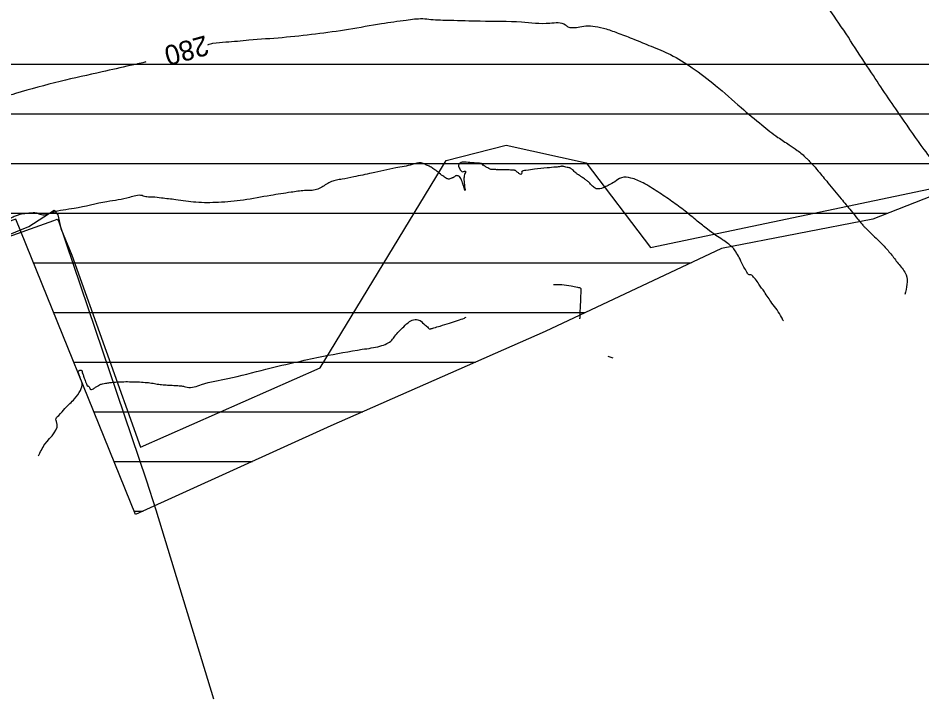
# Model space of a CAD drawing. Extents: x -478464 to -472469, y -1118040 to -1113785.
# Drawn here: x -475759.9 to -475577.7, y -1116153.7 to -1116016.6 of the extents above; entities that cross this region are included whole.
import ezdxf

# ---------------------------------------------------------------- set-up
doc = ezdxf.new("R2010")
doc.units = 0
for name, color, linetype in [('meliorace', 7, 'Continuous'), ('ObPÚ', 7, 'Continuous'), ('VAK_vodovod', 7, 'Continuous'), ('Vrstevnice_hlavni', 7, 'Continuous'), ('Vrstevnice_popis', 7, 'Continuous'), ('Vrstevnice_vedlejsi', 7, 'Continuous')]:
    doc.layers.add(name, color=color, linetype=linetype)

msp = doc.modelspace()

# ---------------------------------------------------------------- linework, layer by layer
at = {"layer": 'meliorace'}
for p, q in [((-475823.626, -1116025.871), (-475330.049, -1116025.871)), ((-475820.488, -1116035.871), (-475318.229, -1116035.871)), ((-475817.351, -1116045.871), (-475309.213, -1116045.871)), ((-475814.214, -1116055.871), (-475584.63, -1116055.871)), ((-475756.779, -1116065.871), (-475624.244, -1116065.871)), ((-475752.725, -1116075.871), (-475645.578, -1116075.871)), ((-475748.672, -1116085.871), (-475667.738, -1116085.871)), ((-475744.619, -1116095.871), (-475690.405, -1116095.871)), ((-475740.565, -1116105.871), (-475712.626, -1116105.871)), ((-475736.512, -1116115.871), (-475734.671, -1116115.871))]:
    msp.add_line(p, q, dxfattribs=at)
msp.add_lwpolyline([(-475572.396, -1116051.092), (-475587.636, -1116057.045), (-475618.116, -1116062.998), (-475653.676, -1116079.667), (-475696.856, -1116098.717), (-475736.226, -1116116.576), (-475760.356, -1116057.045), (-475808.616, -1116073.714), (-475834.016, -1115992.751), (-475842.906, -1115992.751), (-475865.766, -1115949.889), (-475890.404, -1115904.645)], dxfattribs=at)
at = {"layer": 'ObPÚ'}
msp.add_lwpolyline([(-475793.58, -1116073.18), (-475757.75, -1116058.57), (-475752.61, -1116055.25), (-475751.89, -1116056.2), (-475751.3, -1116058.92), (-475749.06, -1116064.34), (-475735.22, -1116102.98), (-475699.02, -1116087.04), (-475673.65, -1116045.26), (-475661.5, -1116042.18), (-475645.43, -1116045.73), (-475632.45, -1116062.75), (-475547.58, -1116044.99)], dxfattribs=at)
at = {"layer": 'VAK_vodovod'}
for points in [[(-475889.88, -1116108.469), (-475889.59, -1116108.35), (-475844.989, -1116090.309), (-475752.719, -1116057.309), (-475752.027, -1116057.077)], [(-475752.027, -1116057.077), (-475751.789, -1116057.42), (-475734.09, -1116109.6), (-475732.17, -1116115.59), (-475720.526, -1116153.696)]]:
    msp.add_lwpolyline(points, dxfattribs=at)
at = {"layer": 'Vrstevnice_hlavni'}
for points in [[(-475467.419, -1116061.098), (-475468.792, -1116057.501), (-475469.738, -1116055.712), (-475470.944, -1116053.934), (-475472.408, -1116052.165), (-475473.807, -1116050.611), (-475475.141, -1116049.271), (-475476.41, -1116048.144), (-475477.843, -1116046.826), (-475479.442, -1116045.315), (-475481.205, -1116043.613), (-475482.586, -1116042.213), (-475483.586, -1116041.117), (-475484.203, -1116040.325), (-475484.728, -1116039.713), (-475485.161, -1116039.283), (-475485.501, -1116039.033), (-475486.369, -1116038.386), (-475487.765, -1116037.341), (-475489.689, -1116035.897), (-475492.224, -1116033.125), (-475495.368, -1116029.023), (-475499.122, -1116023.591), (-475503.303, -1116017.953), (-475507.911, -1116012.107), (-475512.947, -1116006.053), (-475516.528, -1116001.592), (-475518.655, -1115998.722), (-475519.327, -1115997.444), (-475520.958, -1115993.755), (-475523.546, -1115987.656), (-475527.091, -1115979.146), (-475530.068, -1115972.249), (-475532.475, -1115966.964), (-475534.314, -1115963.291), (-475536.317, -1115958.959), (-475538.485, -1115953.967), (-475540.818, -1115948.316), (-475544.241, -1115943.054), (-475548.756, -1115938.18), (-475554.361, -1115933.695), (-475559.671, -1115929.584), (-475564.686, -1115925.845), (-475569.406, -1115922.48), (-475575.428, -1115918.124), (-475582.751, -1115912.777), (-475591.375, -1115906.439), (-475598.808, -1115901.664), (-475605.049, -1115898.45), (-475610.098, -1115896.799), (-475615.266, -1115895.356), (-475620.552, -1115894.121), (-475631.362, -1115892.07)], [(-475721.656, -1116021.921), (-475720.62, -1116021.633), (-475718.031, -1116021.363), (-475713.372, -1116020.965), (-475706.644, -1116020.44), (-475699.945, -1116019.714), (-475693.277, -1116018.786), (-475686.638, -1116017.656), (-475681.664, -1116016.951), (-475678.354, -1116016.672), (-475676.708, -1116016.818), (-475672.839, -1116016.975), (-475666.748, -1116017.142), (-475658.434, -1116017.321), (-475652.719, -1116017.574), (-475649.603, -1116017.901), (-475649.085, -1116018.302), (-475648.228, -1116018.475), (-475647.031, -1116018.42), (-475645.495, -1116018.137), (-475643.612, -1116018.247), (-475641.384, -1116018.748), (-475638.81, -1116019.641), (-475635.789, -1116020.801), (-475632.319, -1116022.229), (-475628.402, -1116023.923), (-475624.07, -1116026.55), (-475619.323, -1116030.11), (-475614.162, -1116034.601), (-475609.969, -1116038.094), (-475606.743, -1116040.588), (-475604.485, -1116042.082), (-475602.862, -1116043.199), (-475601.875, -1116043.937), (-475601.523, -1116044.296), (-475601.083, -1116044.742), (-475600.556, -1116045.273), (-475599.94, -1116045.889), (-475598.642, -1116047.373), (-475596.662, -1116049.725), (-475594.001, -1116052.945), (-475592.012, -1116055.361), (-475590.694, -1116056.974), (-475590.049, -1116057.784), (-475589.53, -1116058.403), (-475589.136, -1116058.832), (-475588.867, -1116059.071), (-475588.149, -1116059.767), (-475586.98, -1116060.92), (-475585.362, -1116062.531), (-475583.813, -1116064.295), (-475582.333, -1116066.213), (-475580.922, -1116068.285), (-475581.168, -1116072.263)], [(-475734.144, -1116025.39), (-475734.387, -1116025.457), (-475737.287, -1116026.117), (-475742.967, -1116027.402), (-475751.425, -1116029.313), (-475760.397, -1116031.757), (-475769.883, -1116034.735), (-475779.883, -1116038.248), (-475786.895, -1116040.679), (-475790.919, -1116042.028), (-475791.955, -1116042.297), (-475792.697, -1116042.52), (-475793.144, -1116042.699), (-475793.297, -1116042.833), (-475793.588, -1116043.024), (-475794.017, -1116043.273), (-475794.584, -1116043.58), (-475795.952, -1116044.161), (-475798.119, -1116045.015), (-475801.087, -1116046.144), (-475804.225, -1116047.876), (-475807.532, -1116050.21), (-475811.009, -1116053.146), (-475814.071, -1116055.662), (-475816.718, -1116057.758), (-475818.95, -1116059.434), (-475821.025, -1116061.042), (-475822.943, -1116062.582), (-475824.704, -1116064.055), (-475826.102, -1116065.24), (-475827.136, -1116066.137), (-475827.806, -1116066.746), (-475828.232, -1116067.209), (-475828.413, -1116067.526), (-475828.351, -1116067.695), (-475828.313, -1116067.833), (-475828.301, -1116067.938), (-475828.314, -1116068.011), (-475828.374, -1116068.106), (-475828.48, -1116068.222), (-475828.632, -1116068.36), (-475828.838, -1116068.557), (-475829.097, -1116068.811), (-475829.411, -1116069.123), (-475829.283, -1116069.23), (-475828.713, -1116069.131), (-475827.701, -1116068.826), (-475826.629, -1116068.71), (-475825.498, -1116068.782), (-475824.306, -1116069.042), (-475823.632, -1116070.151), (-475823.476, -1116072.107), (-475823.837, -1116074.911), (-475824.33, -1116076.913), (-475824.954, -1116078.115), (-475825.71, -1116078.516), (-475826.49, -1116078.935), (-475827.294, -1116079.372), (-475828.122, -1116079.828), (-475829.743, -1116080.299), (-475832.155, -1116080.784), (-475835.36, -1116081.285), (-475837.985, -1116081.623), (-475840.031, -1116081.798), (-475841.497, -1116081.812), (-475842.513, -1116081.989), (-475843.078, -1116082.332), (-475843.194, -1116082.84), (-475843.394, -1116083.435), (-475843.681, -1116084.119), (-475844.052, -1116084.891), (-475844.462, -1116085.311), (-475844.911, -1116085.379), (-475845.399, -1116085.096), (-475845.763, -1116084.899), (-475846.004, -1116084.788), (-475846.121, -1116084.764), (-475846.236, -1116084.79), (-475846.348, -1116084.866), (-475846.459, -1116084.992), (-475846.998, -1116085.894), (-475847.966, -1116087.573), (-475849.364, -1116090.027), (-475850.298, -1116091.666), (-475850.771, -1116092.488), (-475850.781, -1116092.494), (-475850.786, -1116092.51), (-475850.787, -1116092.538), (-475850.784, -1116092.577), (-475850.701, -1116092.72), (-475850.538, -1116092.969), (-475850.294, -1116093.322), (-475849.947, -1116093.789), (-475849.495, -1116094.37), (-475848.939, -1116095.066), (-475848.819, -1116095.385), (-475849.137, -1116095.329)]]:
    msp.add_spline(points, degree=3, dxfattribs=at)
at = {"layer": 'Vrstevnice_vedlejsi'}
msp.add_line((-475641.018, -1116084.677), (-475640.054, -1116085.004), dxfattribs=at)
for points in [[(-475480.151, -1116069.925), (-475480.528, -1116069.421), (-475481.823, -1116067.661), (-475483.652, -1116064.935), (-475486.015, -1116061.242), (-475488.912, -1116056.583), (-475491.25, -1116052.905), (-475493.027, -1116050.207), (-475494.244, -1116048.489), (-475495.061, -1116047.336), (-475495.479, -1116046.748), (-475495.497, -1116046.725), (-475495.829, -1116046.475), (-475496.475, -1116045.999), (-475497.435, -1116045.295), (-475499.886, -1116043.467), (-475503.828, -1116040.516), (-475509.26, -1116036.441), (-475513.121, -1116033.379), (-475515.41, -1116031.328), (-475516.128, -1116030.289), (-475516.97, -1116029.159), (-475517.937, -1116027.939), (-475519.028, -1116026.627), (-475521.605, -1116022.94), (-475525.669, -1116016.877), (-475531.218, -1116008.438), (-475535.677, -1116000.991), (-475539.045, -1115994.534), (-475541.323, -1115989.067), (-475544.201, -1115982.706), (-475547.68, -1115975.451), (-475551.759, -1115967.302), (-475554.612, -1115961.548), (-475556.237, -1115958.188), (-475556.636, -1115957.222), (-475557.22, -1115956.323), (-475557.991, -1115955.491), (-475558.949, -1115954.725), (-475561.753, -1115952.67), (-475566.405, -1115949.326), (-475572.904, -1115944.692), (-475579.584, -1115939.938), (-475586.446, -1115935.063), (-475593.49, -1115930.068), (-475600.006, -1115926.174), (-475605.993, -1115923.382)], [(-475497.37, -1116068.403), (-475497.633, -1116067.979), (-475500.085, -1116064.037), (-475501.869, -1116061.198), (-475502.986, -1116059.46), (-475503.436, -1116058.825), (-475503.924, -1116058.233), (-475504.45, -1116057.685), (-475505.013, -1116057.18), (-475505.755, -1116056.024), (-475506.678, -1116054.215), (-475507.779, -1116051.755), (-475508.673, -1116049.954), (-475509.359, -1116048.814), (-475509.837, -1116048.333), (-475511.119, -1116047.79), (-475513.205, -1116047.187), (-475516.096, -1116046.522), (-475518.059, -1116046.071), (-475519.096, -1116045.833), (-475519.205, -1116045.808), (-475519.283, -1116045.788), (-475519.33, -1116045.772), (-475519.346, -1116045.76), (-475520.304, -1116045.057), (-475522.205, -1116043.664), (-475525.048, -1116041.58), (-475527.874, -1116039.592), (-475530.681, -1116037.698), (-475533.471, -1116035.9), (-475536.828, -1116031.824), (-475540.751, -1116025.472), (-475545.242, -1116016.842), (-475548.836, -1116010.176), (-475551.533, -1116005.475), (-475553.333, -1116002.737), (-475554.692, -1116000.531), (-475555.61, -1115998.855), (-475556.087, -1115997.71), (-475556.784, -1115996.19), (-475557.701, -1115994.295), (-475558.837, -1115992.025), (-475562.469, -1115987.267), (-475568.595, -1115980.022), (-475577.217, -1115970.289), (-475584.87, -1115962.449), (-475591.555, -1115956.502), (-475597.272, -1115952.448), (-475603.006, -1115949.149), (-475608.756, -1115946.607), (-475614.524, -1115944.82), (-475620.596, -1115943.36), (-475626.972, -1115942.227)], [(-475517.572, -1116066.619), (-475517.753, -1116066.428), (-475521.164, -1116062.876), (-475524.777, -1116059.186), (-475527.496, -1116056.526), (-475529.321, -1116054.896), (-475530.252, -1116054.296), (-475531.462, -1116053.606), (-475532.952, -1116052.825), (-475534.721, -1116051.953), (-475536.209, -1116051.042), (-475537.415, -1116050.093), (-475538.339, -1116049.106), (-475539.112, -1116048.345), (-475539.734, -1116047.811), (-475540.205, -1116047.503), (-475540.671, -1116047.258), (-475541.132, -1116047.075), (-475541.589, -1116046.955), (-475543.06, -1116046.13), (-475545.544, -1116044.599), (-475549.042, -1116042.364), (-475551.91, -1116040.528), (-475554.148, -1116039.093), (-475555.755, -1116038.057), (-475557.153, -1116036.738), (-475558.342, -1116035.138), (-475559.321, -1116033.256), (-475562.018, -1116028.66), (-475566.432, -1116021.35), (-475572.564, -1116011.326), (-475579.461, -1116001.664), (-475587.123, -1115992.364), (-475595.552, -1115983.426), (-475602.158, -1115977.054), (-475606.943, -1115973.249), (-475609.906, -1115972.01), (-475614.951, -1115970.845), (-475622.078, -1115969.752), (-475631.287, -1115968.732), (-475641.35, -1115967.924), (-475652.265, -1115967.327), (-475664.034, -1115966.942), (-475672.102, -1115966.665), (-475676.468, -1115966.495), (-475677.132, -1115966.434), (-475678.388, -1115966.326), (-475680.235, -1115966.172), (-475682.675, -1115965.971), (-475688.18, -1115965.51), (-475696.749, -1115964.79)], [(-475546.909, -1116064.851), (-475548.498, -1116064.079), (-475551.049, -1116062.628), (-475553.948, -1116060.801), (-475557.196, -1116058.596), (-475559.728, -1116056.751), (-475561.543, -1116055.266), (-475562.643, -1116054.14), (-475563.681, -1116053.352), (-475564.658, -1116052.9), (-475565.574, -1116052.785), (-475566.693, -1116052.522), (-475568.017, -1116052.111), (-475569.545, -1116051.551), (-475571.597, -1116049.847), (-475574.173, -1116046.997), (-475577.272, -1116043.003), (-475581.846, -1116036.534), (-475587.894, -1116027.591), (-475595.416, -1116016.174), (-475600.541, -1116008.467), (-475603.269, -1116004.469), (-475603.6, -1116004.181), (-475604.124, -1116003.858), (-475604.841, -1116003.499), (-475605.751, -1116003.105), (-475609.228, -1116001.643), (-475615.272, -1115999.112), (-475623.883, -1115995.513), (-475630.473, -1115993.019), (-475635.042, -1115991.631)], [(-475658.86, -1116047.938), (-475659.29, -1116047.586), (-475659.587, -1116047.351), (-475659.75, -1116047.232), (-475659.778, -1116047.229), (-475659.985, -1116047.214), (-475660.371, -1116047.188), (-475660.937, -1116047.15), (-475661.516, -1116047.122), (-475662.11, -1116047.105), (-475662.719, -1116047.097), (-475663.129, -1116047.093), (-475663.34, -1116047.092), (-475663.353, -1116047.093), (-475663.496, -1116047.092), (-475663.77, -1116047.087), (-475664.174, -1116047.079), (-475664.455, -1116047.072), (-475664.613, -1116047.064), (-475664.648, -1116047.056), (-475664.861, -1116046.945), (-475665.254, -1116046.73), (-475665.825, -1116046.412), (-475666.185, -1116046.197), (-475666.335, -1116046.086), (-475666.275, -1116046.078), (-475666.267, -1116046.047), (-475666.312, -1116045.993), (-475666.41, -1116045.917), (-475666.492, -1116045.866), (-475666.558, -1116045.84), (-475666.608, -1116045.839), (-475666.687, -1116045.834), (-475666.797, -1116045.825), (-475666.936, -1116045.813), (-475667.504, -1116045.769), (-475668.501, -1116045.694), (-475669.926, -1116045.588), (-475670.801, -1116045.756), (-475671.126, -1116046.198), (-475670.9, -1116046.915), (-475670.627, -1116047.348), (-475670.308, -1116047.498), (-475669.941, -1116047.363), (-475669.757, -1116047.412), (-475669.755, -1116047.643), (-475669.937, -1116048.057), (-475670.024, -1116048.634), (-475670.018, -1116049.374), (-475669.918, -1116050.278), (-475669.853, -1116050.882), (-475669.823, -1116051.187), (-475669.828, -1116051.193), (-475669.832, -1116051.197), (-475669.833, -1116051.201), (-475669.833, -1116051.204), (-475669.834, -1116051.213), (-475669.835, -1116051.228), (-475669.836, -1116051.249), (-475669.841, -1116051.255), (-475669.848, -1116051.244), (-475669.858, -1116051.218), (-475669.953, -1116050.919), (-475670.131, -1116050.346), (-475670.394, -1116049.501), (-475670.659, -1116048.885), (-475670.926, -1116048.498), (-475671.196, -1116048.341), (-475671.458, -1116048.293), (-475671.713, -1116048.354), (-475671.961, -1116048.524), (-475672.143, -1116048.642), (-475672.26, -1116048.71), (-475672.312, -1116048.727), (-475672.456, -1116048.782), (-475672.694, -1116048.876), (-475673.024, -1116049.008), (-475673.559, -1116048.838), (-475674.297, -1116048.367), (-475675.239, -1116047.594), (-475676.097, -1116046.97), (-475676.869, -1116046.495), (-475677.556, -1116046.167), (-475678.086, -1116045.932), (-475678.459, -1116045.788), (-475678.675, -1116045.737), (-475680.444, -1116046.054), (-475683.767, -1116046.741), (-475688.643, -1116047.797), (-475692.258, -1116048.555), (-475694.611, -1116049.015), (-475695.703, -1116049.177), (-475696.747, -1116049.503), (-475697.742, -1116049.991), (-475698.69, -1116050.643), (-475699.748, -1116051.081), (-475700.917, -1116051.306)], [(-475605.654, -1116077.561), (-475606.012, -1116076.816), (-475607.964, -1116073.949), (-475609.489, -1116071.719), (-475610.587, -1116070.129), (-475611.258, -1116069.176), (-475611.808, -1116068.55), (-475612.235, -1116068.251), (-475612.541, -1116068.279), (-475613.003, -1116067.767), (-475613.622, -1116066.715), (-475614.397, -1116065.123), (-475615.071, -1116063.901), (-475615.643, -1116063.05), (-475616.112, -1116062.569), (-475616.868, -1116061.955), (-475617.91, -1116061.209), (-475619.238, -1116060.33), (-475620.941, -1116059.075), (-475623.02, -1116057.443), (-475625.474, -1116055.434), (-475628.112, -1116053.481), (-475630.935, -1116051.582), (-475633.941, -1116049.738), (-475636.397, -1116048.781), (-475638.3, -1116048.71), (-475639.651, -1116049.526), (-475640.776, -1116050.159), (-475641.674, -1116050.61), (-475642.346, -1116050.877), (-475642.922, -1116050.981), (-475643.401, -1116050.921), (-475643.785, -1116050.697), (-475644.124, -1116050.438), (-475644.419, -1116050.145), (-475644.67, -1116049.817), (-475645.059, -1116049.451), (-475645.586, -1116049.049), (-475646.25, -1116048.609), (-475646.755, -1116048.271), (-475647.099, -1116048.033), (-475647.283, -1116047.896), (-475647.52, -1116047.7), (-475647.81, -1116047.445), (-475648.152, -1116047.13), (-475648.401, -1116046.912), (-475648.557, -1116046.791), (-475648.619, -1116046.767), (-475648.836, -1116046.71), (-475649.209, -1116046.622), (-475649.737, -1116046.503), (-475650.097, -1116046.424), (-475650.288, -1116046.388), (-475650.31, -1116046.393), (-475650.363, -1116046.407), (-475650.448, -1116046.431), (-475650.564, -1116046.465), (-475651.499, -1116046.567), (-475653.254, -1116046.737), (-475655.827, -1116046.975), (-475657.546, -1116047.253), (-475658.41, -1116047.572), (-475658.42, -1116047.931), (-475658.569, -1116048.053), (-475658.86, -1116047.938)], [(-475700.917, -1116051.306), (-475702.197, -1116051.318), (-475704.886, -1116051.643), (-475708.985, -1116052.28), (-475714.492, -1116053.23), (-475719.518, -1116053.691), (-475724.06, -1116053.664), (-475728.121, -1116053.148), (-475731.025, -1116052.804), (-475732.775, -1116052.632), (-475733.368, -1116052.632), (-475733.923, -1116052.581), (-475734.439, -1116052.479), (-475734.917, -1116052.326), (-475737.433, -1116052.681), (-475741.989, -1116053.543), (-475748.583, -1116054.912), (-475753.08, -1116055.776), (-475755.48, -1116056.133), (-475755.782, -1116055.985), (-475756.085, -1116055.883), (-475756.389, -1116055.827), (-475756.695, -1116055.817), (-475757.021, -1116055.823), (-475757.369, -1116055.843), (-475757.738, -1116055.879), (-475758.15, -1116055.919), (-475758.606, -1116055.963), (-475759.106, -1116056.011), (-475759.727, -1116056.173), (-475760.47, -1116056.449), (-475761.333, -1116056.838), (-475762.228, -1116057.313), (-475763.155, -1116057.871), (-475764.112, -1116058.515), (-475765.311, -1116059.165), (-475766.751, -1116059.821), (-475768.433, -1116060.485), (-475770.168, -1116061.086), (-475771.957, -1116061.625), (-475773.799, -1116062.103), (-475775.775, -1116063.076), (-475777.886, -1116064.546), (-475780.13, -1116066.512), (-475781.67, -1116067.847), (-475782.506, -1116068.549), (-475782.636, -1116068.62), (-475782.994, -1116068.848), (-475783.58, -1116069.232), (-475784.394, -1116069.774), (-475785.239, -1116070.426), (-475786.116, -1116071.187), (-475787.025, -1116072.058), (-475787.918, -1116072.909), (-475788.796, -1116073.739), (-475789.657, -1116074.549), (-475790.282, -1116075.298), (-475790.672, -1116075.987), (-475790.825, -1116076.616), (-475790.95, -1116077.06), (-475791.046, -1116077.319), (-475791.114, -1116077.392), (-475791.169, -1116077.452), (-475791.211, -1116077.501), (-475791.24, -1116077.537), (-475791.26, -1116077.563), (-475791.268, -1116077.577), (-475791.267, -1116077.581), (-475791.268, -1116077.585), (-475791.272, -1116077.59), (-475791.278, -1116077.596), (-475791.281, -1116077.6), (-475791.283, -1116077.603), (-475791.283, -1116077.604), (-475791.298, -1116077.632), (-475791.329, -1116077.688), (-475791.375, -1116077.772), (-475793.505, -1116080.848), (-475797.72, -1116086.917), (-475804.02, -1116095.979), (-475806.003, -1116098.98)], [(-475651.968, -1116070.217), (-475650.338, -1116070.231), (-475648.42, -1116070.513), (-475647.138, -1116070.783), (-475646.492, -1116071.04), (-475646.482, -1116071.286), (-475646.516, -1116072.359), (-475646.593, -1116074.258), (-475646.714, -1116076.984), (-475646.724, -1116077.142)], [(-475690.519, -1116083.271), (-475686.971, -1116082.635), (-475685.583, -1116082.139), (-475684.581, -1116081.465), (-475683.965, -1116080.613), (-475683.161, -1116079.699), (-475682.17, -1116078.723), (-475680.991, -1116077.686), (-475679.887, -1116077.28), (-475678.859, -1116077.506), (-475677.906, -1116078.364), (-475677.245, -1116078.928), (-475676.878, -1116079.199), (-475676.804, -1116079.176), (-475676.122, -1116078.971), (-475674.833, -1116078.584), (-475672.936, -1116078.015), (-475671.308, -1116077.477), (-475669.949, -1116076.971), (-475669.6, -1116076.824)], [(-475755.762, -1116104.759), (-475754.48, -1116102.382), (-475752.153, -1116097.799), (-475752.287, -1116097.468), (-475751.723, -1116096.597), (-475750.461, -1116095.186), (-475748.503, -1116093.235), (-475747.342, -1116091.55), (-475746.981, -1116090.13), (-475747.419, -1116088.975), (-475747.69, -1116088.18), (-475747.795, -1116087.744), (-475747.733, -1116087.667), (-475747.651, -1116087.598), (-475747.55, -1116087.537), (-475747.429, -1116087.484), (-475747.326, -1116087.459), (-475747.241, -1116087.464), (-475747.174, -1116087.497), (-475747.111, -1116087.538), (-475747.051, -1116087.585), (-475746.995, -1116087.641), (-475746.964, -1116087.705), (-475746.958, -1116087.778), (-475746.979, -1116087.861), (-475746.875, -1116088.226), (-475746.646, -1116088.875), (-475746.293, -1116089.806), (-475746.026, -1116090.414), (-475745.847, -1116090.697), (-475745.754, -1116090.658), (-475745.644, -1116090.741), (-475745.516, -1116090.949), (-475745.372, -1116091.281), (-475745.096, -1116091.372), (-475744.689, -1116091.224), (-475744.152, -1116090.835), (-475743.672, -1116090.537), (-475743.251, -1116090.329), (-475742.889, -1116090.212), (-475742.268, -1116090.095), (-475741.39, -1116089.98), (-475740.254, -1116089.866), (-475738.942, -1116089.804), (-475737.453, -1116089.794), (-475735.788, -1116089.837), (-475734.301, -1116089.93), (-475732.991, -1116090.073), (-475731.858, -1116090.265), (-475730.683, -1116090.409), (-475729.467, -1116090.504), (-475728.208, -1116090.55), (-475727.187, -1116090.633), (-475726.402, -1116090.752), (-475725.855, -1116090.908), (-475722.932, -1116090.381), (-475717.634, -1116089.17), (-475709.961, -1116087.276), (-475703.537, -1116085.778), (-475698.364, -1116084.678), (-475690.519, -1116083.271)]]:
    msp.add_spline(points, degree=3, dxfattribs=at)

# ---------------------------------------------------------------- texts
at = {"layer": 'Vrstevnice_popis'}
msp.add_text(' 280 ', height=4, rotation=195.52286, dxfattribs=at).set_placement((-475720.724, -1116019.587))

doc.saveas('drawing.dxf')
